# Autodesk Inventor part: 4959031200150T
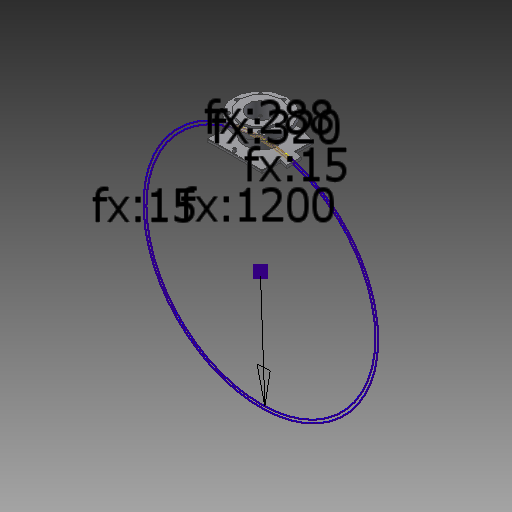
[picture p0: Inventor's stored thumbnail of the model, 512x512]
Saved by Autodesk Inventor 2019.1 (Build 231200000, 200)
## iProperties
Created: 2017-10
Part Number: 4959031200150T
Material: Generic
Document SubType Name: Modeling
Designer: KIM
Density: 1 g/cm^3
Appearance: Default
Description: PLASSON FLANGED BRANCH SADDLE 1200x150
Mass: 2339.99 g
Surface Area: 3251.55 cm^2
Volume: 2339.99 cm^3
Author: KIM
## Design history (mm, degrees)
sketch "Sketch1"
  geometry: L1 (-144, 597.904)-(-144, 582.464); L2 (144, 597.904)-(144, 582.464); A1 r 600 centre (0, 0) between (-144, 582.464) and (144, 582.464); A2 r 615 centre (0, 0) between (-144, 597.904) and (144, 597.904); 1 further point
  constraints: 4 end point, 4 point on circle, 2 centre point, 2 parallel, 1 coincident, 1 vertical
  dimensions: "d0" = 1200 diameter of A1 (= d_); "d1" = 15 radial gap between concentric circles of A1 A2 (= x_); "d2" = 288 distance between parallel lines of L2 L1 (derived)
extrude "Extrusion1" new body sketch "Sketch1" stored distance "d3" = 300 (= L_); taper "d4" = 0 deg
sketch "Sketch2"
  geometry: L1 (144, 582.464)-(144, 597.904) reference; L2 (176, 589.278)-(176, 574.278); L3 (-144, 597.904)-(-144, 582.464) reference; L4 (176, 574.278)-(173.794, 574.278); A1 r 615 centre (0, 0) between (144, 597.904) and (-144, 597.904) reference; A2 r 600 centre (0, 0) between (144, 582.464) and (-144, 582.464) reference; A3 r 600 centre (0, 0) between (144, 582.464) and (-144, 582.464) reference; A4 r 615 centre (0, 0) between (144, 597.904) and (-144, 597.904) reference; A5 r 615 centre (0, 0) between (176, 589.278) and (144, 597.904); A6 r 600 centre (0, 0) between (173.794, 574.278) and (144, 582.464); 3 further points
  constraints: 4 end point, 4 point on circle, 2 centre point, 2 coincident, 1 horizontal, 1 vertical, 11 other
  dimensions: "d67" = 15 distance of L2.start L2.end (derived); "d72" = 320 distance between parallel lines of L2 L3 (derived)
extrude "Extrusion2" join sketch "Sketch2" stored distance "d6" = 75 (= 0.25 x L_); taper "d7" = 0 deg
workplane "Work Plane1"
sketch "Sketch4"
  geometry: C1 r 7 at (0, 135); 1 further point
  constraints: 1 centre point
  dimensions: "d13" = 14 diameter of C1; "d14" = 135 distance of point (0, 0) C1.centre (= 0.45 x L_)
extrude "Extrusion4" join sketch "Sketch4" stored distance "d15" = 75 (= 0.25 x L_); taper "d16" = 5 deg
sketch "Sketch5"
  geometry: C1 r 7 at (0, 0) reference; C2 r 5 at (0, 0); C3 r 2 at (0, 0); 1 further point
  constraints: 2 centre point, 2 coincident
  dimensions: "d17" = 10 diameter of C2; "d18" = 4 diameter of C3
extrude "Extrusion5" cut sketch "Sketch5" distance "d19" = 14; taper "d20" = 0 deg
sketch "Sketch6"
  geometry: C1 r 2 at (0, 0) reference; 1 further point
extrude "Extrusion6" cut sketch "Sketch6" distance "d21" = 3; taper "d22" = 0 deg
mirror "Mirror2"
workplane "Work Plane2"
sketch "Sketch10"
  geometry: L1 (144, 75)-(144, -150); L2 (-144, -150)-(-144, 225.02); L3 (0, -150)-(144, -150); L4 (144, 150)-(144, -150) reference; L5 (-144, -150)-(-144, -37.5) reference; L6 (-144, -150)-(144, -150) reference; A1 r 698.7 centre (0, 548.7) between (-144, -135) and (144, -135); 1 further point; 1 other entity
  constraints: 6 end point, 3 collinear, 3 point on circle, 2 point on line, 1 centre point, 1 horizontal, 1 horizontal alignment, 1 tangent, 1 other
  dimensions: "d36" = 135 vertical distance of point (0, 0) A1.end (= 0.45 x L_)
extrude "Extrusion10" cut sketch "Sketch10" extent not by distance; stored distance "d37" = 10; taper "d38" = 0 deg
mirror "Mirror3"
mirror "Mirror4"
fillet "Fillet4" dims "d39" = 2
sketch "Sketch11"
  geometry: L1 (0, 0)-(731, 0); L2 (615, -148)-(615, 148) reference; L3 (665.5, 65.5)-(731, 65.5); L4 (731, 65.5)-(731, 106); L5 (731, 106)-(719.8, 106); L6 (719.8, 106)-(719.8, 142.5); L7 (719.8, 142.5)-(695.8, 142.5); L8 (695.8, 142.5)-(695.8, 84.8); L9 (695.8, 84.8)-(665.5, 84.8); L10 (600, 8)-(706.7, 8); L11 (706.7, 8)-(706.7, 5.2); L12 (706.7, 5.2)-(600, 5.2); L13 (600, 5.2)-(600, 8); L14 (600, 148)-(600, -148) reference; L15 (665.5, 65.5)-(665.5, 84.8); 2 further points
  constraints: 26 end point, 7 perpendicular, 2 horizontal, 2 parallel, 1 collinear, 1 vertical, 1 vertical alignment
  dimensions: "d41" = 131 diameter of L3 L1 (= DN_); "d42" = 212 diameter of L5 L1 (= d_1); "d43" = 285 diameter of L7 L1 (= D_1); "d44" = 104.8 distance between parallel lines of L2 L6 (= 0.8 x H_); "d46" = 169.6 diameter of L9 L1 (= 0.8 x d_1); "d47" = 16 diameter of L10 L1 (= D_); "d48" = 10.4 diameter of L12 L1 (= 0.65 x D_); "d49" = 91.7 distance between parallel lines of L2 L11 (= 0.7 x H_); "d61" = 24 distance of L6.end L7.end (= t_); "d66" = 131 distance between parallel lines of L14 L4 (derived); "d68" = 65.5 distance between parallel lines of L14 L15 (derived)
revolve "Revolution1" sketch "Sketch11" stored, may be unused: angle "d50" = 90 deg
sketch "Sketch12"
  geometry: C1 r 612 at (0, 0); 1 further point
  constraints: 1 centre point, 1 coincident
  dimensions: "d51" = 1224 diameter of C1 (= 1.02 x d_)
extrude "Extrusion11" cut sketch "Sketch12" extent not by distance; stored distance "d52" = 0; taper "d53" = 0 deg
sketch "Sketch13"
  geometry: C1 r 11 at (120, 0); 1 further point
  constraints: 1 centre point, 1 horizontal alignment
  dimensions: "d54" = 22 diameter of C1 (= s_); "d55" = 120 distance of point (0, 0) C1.centre (= 0.5 x Dp_)
extrude "Extrusion12" cut sketch "Sketch13" stored distance "d56" = 10; taper "d57" = 0 deg
pattern_circular "Circular Pattern1" dims angle "d59" = 360 deg
sketch "Sketch14"
  geometry: C1 r 5.2 at (0, 0) reference; 1 further point
extrude "Extrusion13" cut sketch "Sketch14" extent not by distance; stored distance "d62" = 10; taper "d63" = 0 deg
combine "Combine1"
  body "Solid1"
sketch "Sketch15"
  geometry: C1 r 65.5 at (0, 0) reference; C2 r 84.8 at (0, 0) reference; 1 further point
extrude "Extrusion14" join sketch "Sketch15" stored distance "d69" = 10; taper "d70" = 0 deg
fillet "Fillet5" dims "d71" = 2
node "Projected Loop2"
body "Solid2"
node "Projected Loop4"
other parameters: "d_" = 1200 [user parameter; used in 4 equation terms], "d_1" = 212 [user parameter; used in 2 equation terms], "H_" = 131 [user parameter; used in 3 equation terms], "L_" = 300 [user parameter; used in 5 equation terms], "x_" = 15 [user parameter; used in 2 equation terms], "d12" = 625.6 (computed from d_), "d23" = 746 (= x_ + 0.5 x d_ + H_), "D_" = 16 [user parameter; used in 2 equation terms], "DN_" = 131 [user parameter; used in 1 equation term], "D_1" = 285 [user parameter; used in 1 equation term], "t_" = 24 [user parameter; used in 1 equation term], "s_" = 22 [user parameter; used in 1 equation term]
